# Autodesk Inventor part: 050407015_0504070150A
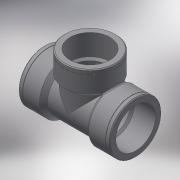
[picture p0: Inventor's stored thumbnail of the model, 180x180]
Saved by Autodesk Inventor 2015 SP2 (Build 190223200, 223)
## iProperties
Created: 2017-05
Part Number: 050407015_0504070150A
Material: Generic
Description: PLASSON THREADED TEE 1.1/2"
Document SubType Name: Modeling
Designer: KIM
Density: 1 g/cm^3
Appearance: Default
Author: KIM
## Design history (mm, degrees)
derived "050407.ipt"
feature "Solid1::050407.ipt"
tag "TaggingFeature1"
body "Solid1"
other parameters: "d0" = 54, "d2" = 0.5, "d3" = 0.5, "d4" = 58.2985, "d5" = 44.845, "d6" = 25, "d7" = 135 deg, "d8" = 28.75, "d9" = 4.79167, "d19" = 0.8969, "d27" = 25, "d30" = 40.3605, "d31" = 49.3295, "d33" = 180 deg, "d39" = 0, "d45" = 0, "d46" = 49.3295, "d48" = 0, "d50" = 0, "d51" = 1.34535, "Rp_" = 44.845, "H_" = 108, "l_2" = 25
